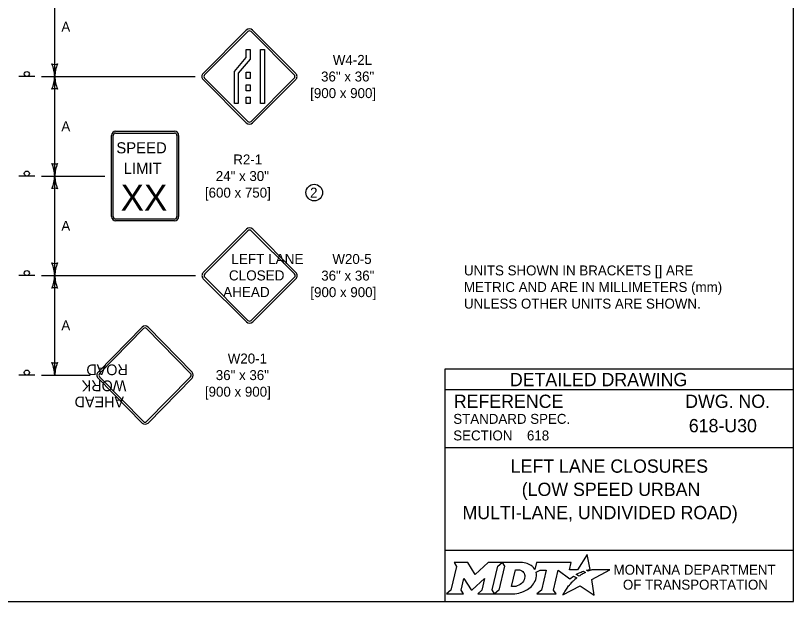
# Model space of a CAD drawing. Extents: x 49991.4 to 50021, y 49987.6 to 50011.4.
# Drawn here: x 50003.928 to 50008.615, y 50000.062 to 50003.594 of the extents above; entities that cross this region are included whole.
import ezdxf

# ---------------------------------------------------------------- set-up
doc = ezdxf.new("R2010")
doc.units = 0
for name, color, linetype in [('Level 1', 7, 'Continuous'), ('Level 2', 7, 'Continuous'), ('Level 3', 7, 'Continuous')]:
    doc.layers.add(name, color=color, linetype=linetype)

msp = doc.modelspace()

# ---------------------------------------------------------------- linework, layer by layer
at = {"layer": 'Level 1'}
for p, q in [((50005.0574, 50003.2453), (50005.318, 50003.5059)), ((50005.0662, 50003.2365), (50005.3268, 50003.4971)), ((50005.3466, 50003.4972), (50005.607, 50003.2365)), ((50005.3554, 50003.506), (50005.6158, 50003.2452)), ((50005.3172, 50003.3404), (50005.3172, 50003.389)), ((50005.3172, 50003.389), (50005.3407, 50003.3889)), ((50005.3407, 50003.3889), (50005.3406, 50003.3318)), ((50005.4036, 50003.0647), (50005.4038, 50003.3889)), ((50005.4038, 50003.3889), (50005.4273, 50003.3889)), ((50005.4273, 50003.3889), (50005.427, 50003.0647)), ((50005.2461, 50003.2566), (50005.3172, 50003.3404)), ((50005.3406, 50003.3318), (50005.2696, 50003.2474)), ((50005.246, 50003.0642), (50005.2461, 50003.2566)), ((50005.2696, 50003.2474), (50005.2695, 50003.0642)), ((50005.3171, 50003.2147), (50005.3171, 50003.2523)), ((50005.3171, 50003.2523), (50005.3406, 50003.2523)), ((50005.3406, 50003.2523), (50005.3405, 50003.2147)), ((50004.0436, 50003.2267), (50003.9476, 50003.2267)), ((50005.318, 50002.9473), (50005.0574, 50003.2081)), ((50005.3267, 50002.956), (50005.0661, 50003.2168)), ((50005.3405, 50003.2147), (50005.3171, 50003.2147)), ((50005.6071, 50003.2169), (50005.3466, 50002.956)), ((50005.6159, 50003.2081), (50005.3554, 50002.9472)), ((50005.317, 50003.1394), (50005.317, 50003.1771)), ((50005.317, 50003.1771), (50005.3405, 50003.1771)), ((50005.3405, 50003.1771), (50005.3405, 50003.1394)), ((50005.3405, 50003.1394), (50005.317, 50003.1394)), ((50005.2695, 50003.0642), (50005.246, 50003.0642)), ((50005.317, 50003.0642), (50005.317, 50003.1018)), ((50005.317, 50003.1018), (50005.3404, 50003.1018)), ((50005.3404, 50003.0642), (50005.317, 50003.0642)), ((50005.3404, 50003.1018), (50005.3404, 50003.0642)), ((50005.427, 50003.0647), (50005.4036, 50003.0647)), ((50004.5054, 50002.382), (50004.5054, 50002.8714)), ((50004.5159, 50002.382), (50004.5159, 50002.8714)), ((50004.5307, 50002.8968), (50004.8851, 50002.8968)), ((50004.5307, 50002.8862), (50004.8851, 50002.8862)), ((50004.7079, 50002.8968), (50004.7079, 50002.8968)), ((50004.8999, 50002.8714), (50004.8999, 50002.382)), ((50004.9104, 50002.8714), (50004.9104, 50002.382)), ((50004.0436, 50002.6267), (50003.9476, 50002.6267)), ((50004.8851, 50002.3672), (50004.5307, 50002.3672)), ((50004.8851, 50002.3566), (50004.5307, 50002.3566)), ((50005.3193, 50002.306), (50005.0586, 50002.0453)), ((50005.3193, 50002.306), (50005.3193, 50002.306)), ((50005.6172, 50002.0453), (50005.3565, 50002.306)), ((50005.3281, 50002.2972), (50005.0674, 50002.0365)), ((50005.3281, 50002.2972), (50005.3281, 50002.2972)), ((50005.6084, 50002.0365), (50005.3477, 50002.2972)), ((50004.0436, 50002.0267), (50003.9476, 50002.0267)), ((50005.3379, 50002.0267), (50005.3379, 50002.0267)), ((50005.3379, 50002.0267), (50005.3379, 50002.0267)), ((50005.3379, 50002.0267), (50005.3379, 50002.0267)), ((50005.0586, 50002.0081), (50005.3193, 50001.7474)), ((50005.0674, 50002.0169), (50005.3281, 50001.7562)), ((50005.3477, 50001.7562), (50005.6084, 50002.0169)), ((50005.3565, 50001.7474), (50005.6172, 50002.0081)), ((50004.4246, 50001.4449), (50004.6898, 50001.7156)), ((50004.4334, 50001.4362), (50004.6986, 50001.7069)), ((50004.7172, 50001.7069), (50004.9824, 50001.4362)), ((50004.7261, 50001.7156), (50004.9912, 50001.4449)), ((50004.0436, 50001.4267), (50003.9476, 50001.4267)), ((50004.6986, 50001.1466), (50004.4334, 50001.4173)), ((50004.9824, 50001.4173), (50004.7172, 50001.1466)), ((50004.6898, 50001.1379), (50004.4246, 50001.4086)), ((50004.9912, 50001.4086), (50004.7261, 50001.1379))]:
    msp.add_line(p, q, dxfattribs=at)
msp.add_lwpolyline([(50008.6146, 50011.2628), (50000.3356, 50011.2628), (50000.3356, 50000.0624), (50008.6146, 50000.0624)], close=True, dxfattribs=at)
for centre in [(50003.9956, 50003.2419), (50003.9956, 50002.6419), (50003.9956, 50002.0419), (50003.9956, 50001.4419)]:
    msp.add_circle(centre, 0.0152, dxfattribs=at)
for centre, radius, start, end in [((50005.3366, 50003.4873), 0.0263, 45.0001, 134.9999), ((50005.3367, 50003.4874), 0.0139, 45.0001, 134.9999), ((50005.0761, 50003.2267), 0.0263, 134.9999, 225.0001), ((50005.5974, 50003.2267), 0.0263, 314.9999, 45.0001), ((50005.0761, 50003.2267), 0.0139, 134.9999, 225.0001), ((50005.5974, 50003.2267), 0.0139, 314.9999, 45.0001), ((50005.3367, 50002.966), 0.0263, 225.0001, 314.9999), ((50005.3367, 50002.966), 0.0139, 225.0001, 314.9999), ((50004.5307, 50002.8714), 0.0253, 90, 180), ((50004.5307, 50002.8714), 0.0148, 90, 180), ((50004.8851, 50002.8714), 0.0253, 0, 90), ((50004.8851, 50002.8714), 0.0148, 0, 90), ((50004.5307, 50002.382), 0.0253, 180, 270), ((50004.5307, 50002.382), 0.0148, 180, 270), ((50004.8851, 50002.382), 0.0148, 270, 360), ((50004.8851, 50002.382), 0.0253, 270, 360), ((50005.3379, 50002.2874), 0.0263, 45.0001, 134.9999), ((50005.3379, 50002.2874), 0.0139, 45.0001, 134.9999), ((50005.0772, 50002.0267), 0.0263, 134.9999, 225.0001), ((50005.0772, 50002.0267), 0.0139, 134.9999, 225.0001), ((50005.5986, 50002.0267), 0.0139, 314.9999, 45.0001), ((50005.5986, 50002.0267), 0.0263, 314.9999, 45.0001), ((50005.3379, 50001.766), 0.0263, 225.0001, 314.9999), ((50005.3379, 50001.766), 0.0139, 225.0001, 314.9999)]:
    msp.add_arc(centre, radius, start, end, dxfattribs=at)
for centre, major_axis, ratio, start_param, end_param in [((50004.7079, 50001.6974), (0, 0.0258), 0.98963, 5.497787, 7.068583), ((50004.7079, 50001.6974), (0, 0.0134), 0.98, 5.497787, 7.068583), ((50004.4427, 50001.4267), (0, 0.0258), 0.98963, 0.785394, 2.356194), ((50004.4427, 50001.4267), (0, 0.0134), 0.98, 0.785394, 2.356194), ((50004.9731, 50001.4267), (0, 0.0134), 0.98, 3.926991, 5.497787), ((50004.9731, 50001.4267), (0, 0.0258), 0.98963, 3.926991, 5.497787), ((50004.7079, 50001.1561), (0, -0.0258), 0.98963, 5.497795, 7.068583), ((50004.7079, 50001.1561), (0, -0.0134), 0.98, 5.497795, 7.068583)]:
    msp.add_ellipse(centre, major_axis=major_axis, ratio=ratio, start_param=start_param, end_param=end_param, dxfattribs=at)
at = {"layer": 'Level 2'}
for p, q in [((50008.6146, 50001.4624), (50006.5146, 50001.4624)), ((50006.5146, 50001.4624), (50006.5146, 50000.0624)), ((50008.6146, 50001.3374), (50006.5146, 50001.3374)), ((50008.2507, 50001.1223), (50008.2507, 50001.1223)), ((50007.0089, 50001.0629), (50007.0089, 50001.0629)), ((50008.6146, 50000.9874), (50006.5146, 50000.9874)), ((50007.5646, 50000.7383), (50007.5646, 50000.7383)), ((50008.6146, 50000.3693), (50006.5146, 50000.3693))]:
    msp.add_line(p, q, dxfattribs=at)
for points in [[(50007.3771, 50000.2447), (50007.3668, 50000.2503), (50007.3784, 50000.2531), (50007.39, 50000.2551), (50007.3726, 50000.3452), (50007.3131, 50000.2539), (50007.2658, 50000.2532), (50007.2761, 50000.2973), (50007.0669, 50000.2974), (50007.0568, 50000.2549), (50007.051, 50000.2632)], [(50006.5701, 50000.2974), (50006.5842, 50000.274), (50006.5507, 50000.1307), (50006.525, 50000.1082), (50006.6266, 50000.1082), (50006.6131, 50000.131), (50006.6293, 50000.2011), (50006.673, 50000.1321), (50006.6783, 50000.1321), (50006.7534, 50000.2016), (50006.737, 50000.1305), (50006.7123, 50000.1085), (50006.8139, 50000.1085), (50006.8001, 50000.1318), (50006.8333, 50000.2742)], [(50006.8333, 50000.2742), (50006.8586, 50000.2974), (50006.7762, 50000.2974), (50006.6966, 50000.2244), (50006.6521, 50000.2971), (50006.5701, 50000.2974)], [(50006.9722, 50000.2974), (50006.8586, 50000.2974), (50006.8733, 50000.2745), (50006.8394, 50000.1307), (50006.8139, 50000.1085), (50006.9245, 50000.1085)], [(50006.9962, 50000.2107), (50006.995, 50000.2026), (50006.9918, 50000.1933), (50006.9876, 50000.1851), (50006.982, 50000.1776), (50006.9755, 50000.1707), (50006.9676, 50000.1644), (50006.9593, 50000.1597), (50006.9502, 50000.1558), (50006.9411, 50000.1535), (50006.9319, 50000.1526), (50006.916, 50000.1526), (50006.9396, 50000.2526), (50006.9556, 50000.2526), (50006.9632, 50000.252), (50006.9708, 50000.2501), (50006.9774, 50000.2471), (50006.9835, 50000.2429), (50006.9883, 50000.2379), (50006.992, 50000.2319), (50006.9947, 50000.2257), (50006.9963, 50000.2183), (50006.9963, 50000.2153), (50006.9962, 50000.2107)], [(50007.0636, 50000.2383), (50007.0882, 50000.2514), (50007.1251, 50000.2514), (50007.0965, 50000.1309), (50007.069, 50000.1082), (50007.1852, 50000.1082), (50007.1682, 50000.1311), (50007.1964, 50000.2513), (50007.2677, 50000.1996), (50007.2888, 50000.2147), (50007.3085, 50000.2038)], [(50007.2527, 50000.1479), (50007.2374, 50000.1235), (50007.2327, 50000.116), (50007.2269, 50000.1074), (50007.2246, 50000.1031), (50007.3299, 50000.1562), (50007.4138, 50000.1011), (50007.4007, 50000.1938), (50007.5076, 50000.2522), (50007.4583, 50000.253), (50007.4282, 50000.2534), (50007.4074, 50000.2537), (50007.4006, 50000.2522), (50007.3957, 50000.251), (50007.3873, 50000.2487), (50007.3771, 50000.2447)], [(50007.3267, 50000.2171), (50007.3243, 50000.2154), (50007.306, 50000.225), (50007.3163, 50000.2307), (50007.3204, 50000.2329), (50007.329, 50000.2369), (50007.3347, 50000.2395), (50007.3426, 50000.2425), (50007.3499, 50000.2452), (50007.3617, 50000.2378), (50007.3577, 50000.2357), (50007.3531, 50000.2332), (50007.3489, 50000.231), (50007.3439, 50000.2281), (50007.342, 50000.227), (50007.3393, 50000.2254), (50007.3368, 50000.224), (50007.3345, 50000.2224), (50007.3319, 50000.2206), (50007.3292, 50000.2188), (50007.3267, 50000.2171)], [(50007.2666, 50000.164), (50007.2666, 50000.164)], [(50006.9702, 50000.1158), (50006.9786, 50000.1184), (50006.9916, 50000.1238), (50007.012, 50000.1348)]]:
    msp.add_lwpolyline(points, dxfattribs=at)
msp.add_circle((50005.7273, 50002.5267), 0.0501, dxfattribs=at)
for centre, radius, start, end in [((50006.9953, 50000.219), 0.0709, 339.5329, 15.8582), ((50006.9513, 50000.2363), 0.1183, 300.9103, 339.1383)]:
    msp.add_arc(centre, radius, start, end, dxfattribs=at)
for centre, major_axis, ratio, start_param, end_param in [((50006.9701, 50000.25), (0.0834, -0.0037), 0.568097, 0.61298, 1.570796), ((50007.0257, 50000.2573), (0.0361, -0.0295), 0.469099, 1.225588, 1.570796), ((50007.2974, 50000.1941), (-0.0112, -0.0097), 0.021651, 3.157348, 6.283185), ((50007.2597, 50000.1559), (-0.00694, -0.00806), 0.008222, 0, 3.137361), ((50007.2764, 50000.1742), (-0.0098, -0.0102), 0.016458, 3.141593, 6.279097), ((50006.9248, 50000.2568), (0, 0.1484), 0.987302, 3.139398, 3.456847)]:
    msp.add_ellipse(centre, major_axis=major_axis, ratio=ratio, start_param=start_param, end_param=end_param, dxfattribs=at)
at = {"layer": 'Level 3'}
for p, q in [((50004.1636, 50003.2267), (50004.1636, 50003.8267)), ((50004.0836, 50003.2267), (50005.0098, 50003.2267)), ((50004.1636, 50002.6267), (50004.1636, 50003.2267)), ((50004.0836, 50002.6267), (50004.4654, 50002.6267)), ((50004.1636, 50002.0267), (50004.1636, 50002.6267)), ((50004.0836, 50002.0267), (50005.0109, 50002.0267)), ((50004.1636, 50001.4267), (50004.1636, 50002.0267)), ((50004.0836, 50001.4267), (50004.3772, 50001.4267))]:
    msp.add_line(p, q, dxfattribs=at)
for centre, radius, start, end in [((50004.1636, 50003.3549), 0.0548, 252.1388, 287.8612), ((50003.9309, 50003.2152), 0.233, 2.8273, 22.0772), ((50004.3858, 50003.2175), 0.2223, 157.456, 177.6395), ((50003.9415, 50003.2359), 0.2223, 337.456, 357.6395), ((50004.3963, 50003.2382), 0.233, 182.8273, 202.0772), ((50004.1636, 50003.0985), 0.0548, 72.1388, 107.8612), ((50004.1636, 50002.7549), 0.0548, 252.1388, 287.8612), ((50003.9309, 50002.6152), 0.233, 2.8273, 22.0772), ((50004.3858, 50002.6175), 0.2223, 157.456, 177.6395), ((50003.9415, 50002.6359), 0.2223, 337.456, 357.6395), ((50004.3963, 50002.6382), 0.233, 182.8273, 202.0772), ((50004.1636, 50002.4985), 0.0548, 72.1388, 107.8612), ((50004.1636, 50002.1549), 0.0548, 252.1388, 287.8612), ((50003.9309, 50002.0152), 0.233, 2.8273, 22.0772), ((50004.3858, 50002.0175), 0.2223, 157.456, 177.6395), ((50003.9415, 50002.0359), 0.2223, 337.456, 357.6395), ((50004.3963, 50002.0382), 0.233, 182.8273, 202.0772), ((50004.1636, 50001.8985), 0.0548, 72.1388, 107.8612), ((50004.1636, 50001.5549), 0.0548, 252.1388, 287.8612), ((50003.9309, 50001.4152), 0.233, 2.8273, 22.0772), ((50004.3858, 50001.4175), 0.2223, 157.456, 177.6395)]:
    msp.add_arc(centre, radius, start, end, dxfattribs=at)

# ---------------------------------------------------------------- texts
at = {"layer": 'Level 1'}
for s, height, p in [('SPEED', 0.06695, (50004.5348, 50002.7635)), ('LIMIT', 0.06695, (50004.5791, 50002.6397)), ('XX', 0.15773, (50004.5608, 50002.4177)), ('LEFT LANE', 0.06086, (50005.2279, 50002.0968)), ('CLOSED', 0.06086, (50005.2132, 50001.9974)), ('  AHEAD', 0.06086, (50005.1331, 50001.897))]:
    msp.add_text(s, height=height, dxfattribs=at).set_placement(p)
for s, p in [('ROAD', (50004.6037, 50001.4912)), ('WORK', (50004.5947, 50001.3945)), ('AHEAD', (50004.5809, 50001.2977))]:
    msp.add_text(s, height=0.06453, rotation=180, dxfattribs=at).set_placement(p)
at = {"layer": 'Level 2'}
for s, height, p in [('A', 0.06, (50004.2036, 50003.4967)), ('W4-2L', 0.06, (50005.8393, 50003.2967)), ('36" x 36"', 0.06, (50005.7684, 50003.1967)), ('[900 x 900]', 0.06, (50005.7029, 50003.0967)), ('A', 0.06, (50004.2036, 50002.8967)), ('R2-1', 0.06, (50005.2396, 50002.6967)), ('24" x 30"', 0.06, (50005.1341, 50002.5967)), ('[600 x 750]', 0.06, (50005.0685, 50002.4967)), ('2', 0.06, (50005.7023, 50002.4968)), ('A', 0.06, (50004.2036, 50002.2967)), ('W20-5', 0.06, (50005.8367, 50002.0967)), ('UNITS SHOWN IN BRACKETS [] ARE ', 0.06, (50006.6294, 50002.0278)), ('36" x 36"', 0.06, (50005.7696, 50001.9967)), ('METRIC AND ARE IN MILLIMETERS (mm) ', 0.06, (50006.6294, 50001.9278)), ('[900 x 900]', 0.06, (50005.704, 50001.8967)), ('UNLESS OTHER UNITS ARE SHOWN.', 0.06, (50006.6294, 50001.8278)), ('A', 0.06, (50004.2036, 50001.6967)), ('W20-1', 0.06, (50005.2063, 50001.4967)), ('36" x 36"', 0.06, (50005.1341, 50001.3967)), ('DETAILED DRAWING', 0.0799, (50006.9063, 50001.3599)), ('[900 x 900]', 0.06, (50005.0685, 50001.2967)), ('REFERENCE', 0.08, (50006.5682, 50001.229)), ('DWG. NO.', 0.08, (50007.9624, 50001.229)), ('STANDARD SPEC.', 0.06, (50006.5649, 50001.133)), ('618-U30', 0.08, (50007.9841, 50001.0823)), ('SECTION', 0.06, (50006.5649, 50001.033)), ('618', 0.06, (50007.0089, 50001.0329)), ('LEFT LANE CLOSURES', 0.08, (50006.911, 50000.8383)), ('(LOW SPEED URBAN ', 0.08, (50006.9775, 50000.6983)), ('MULTI-LANE, UNDIVIDED ROAD)', 0.08, (50006.6207, 50000.5583)), ('MONTANA DEPARTMENT', 0.06, (50007.5308, 50000.2236)), ('OF TRANSPORTATION', 0.06, (50007.587, 50000.1336))]:
    msp.add_text(s, height=height, dxfattribs=at).set_placement(p)

doc.saveas('drawing.dxf')
